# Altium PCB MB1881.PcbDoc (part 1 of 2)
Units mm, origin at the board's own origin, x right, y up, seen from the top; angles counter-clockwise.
Board outline 150 x 109 mm, 4 copper layers (Top Layer, Layer 1, Layer 2, Bottom Layer), stack 1.782 mm thick; 66 components, 175 nets, 880 pads, 302 vias.
Unrouted connection lines stored in the file: 35.
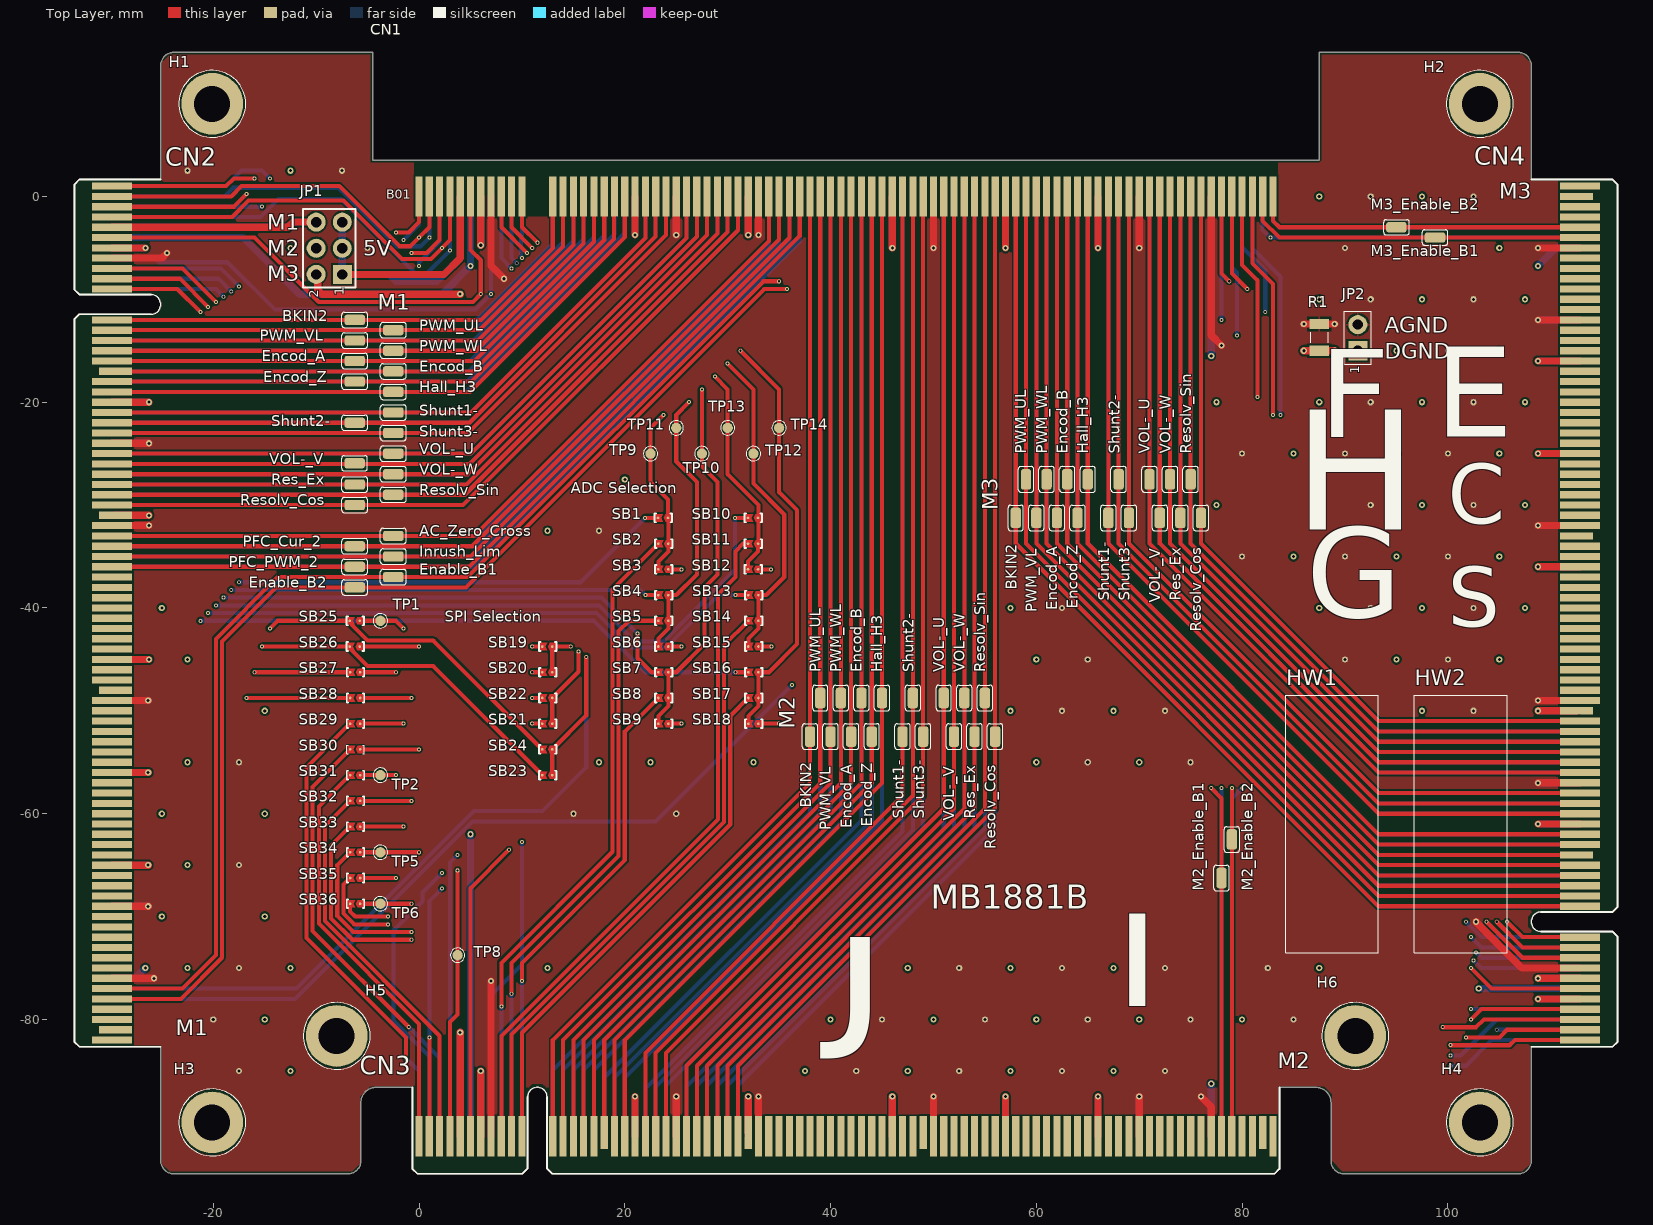
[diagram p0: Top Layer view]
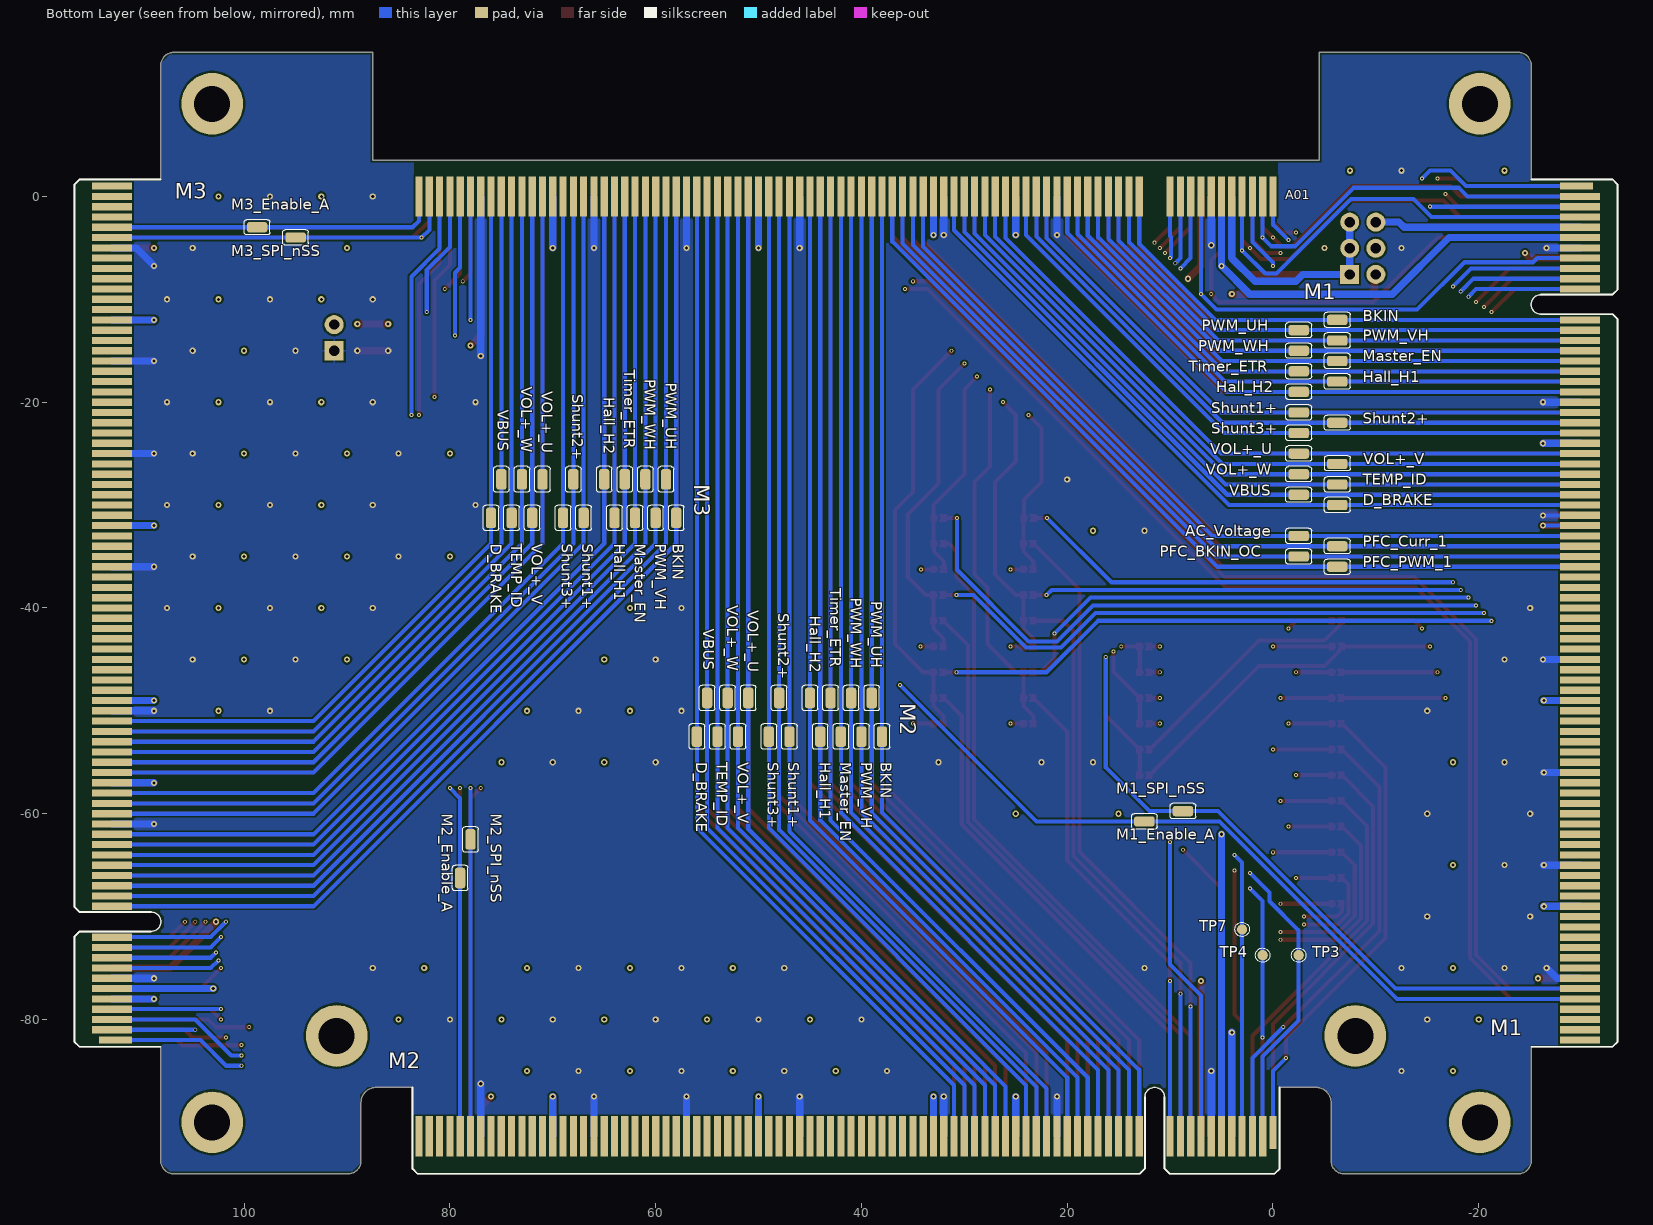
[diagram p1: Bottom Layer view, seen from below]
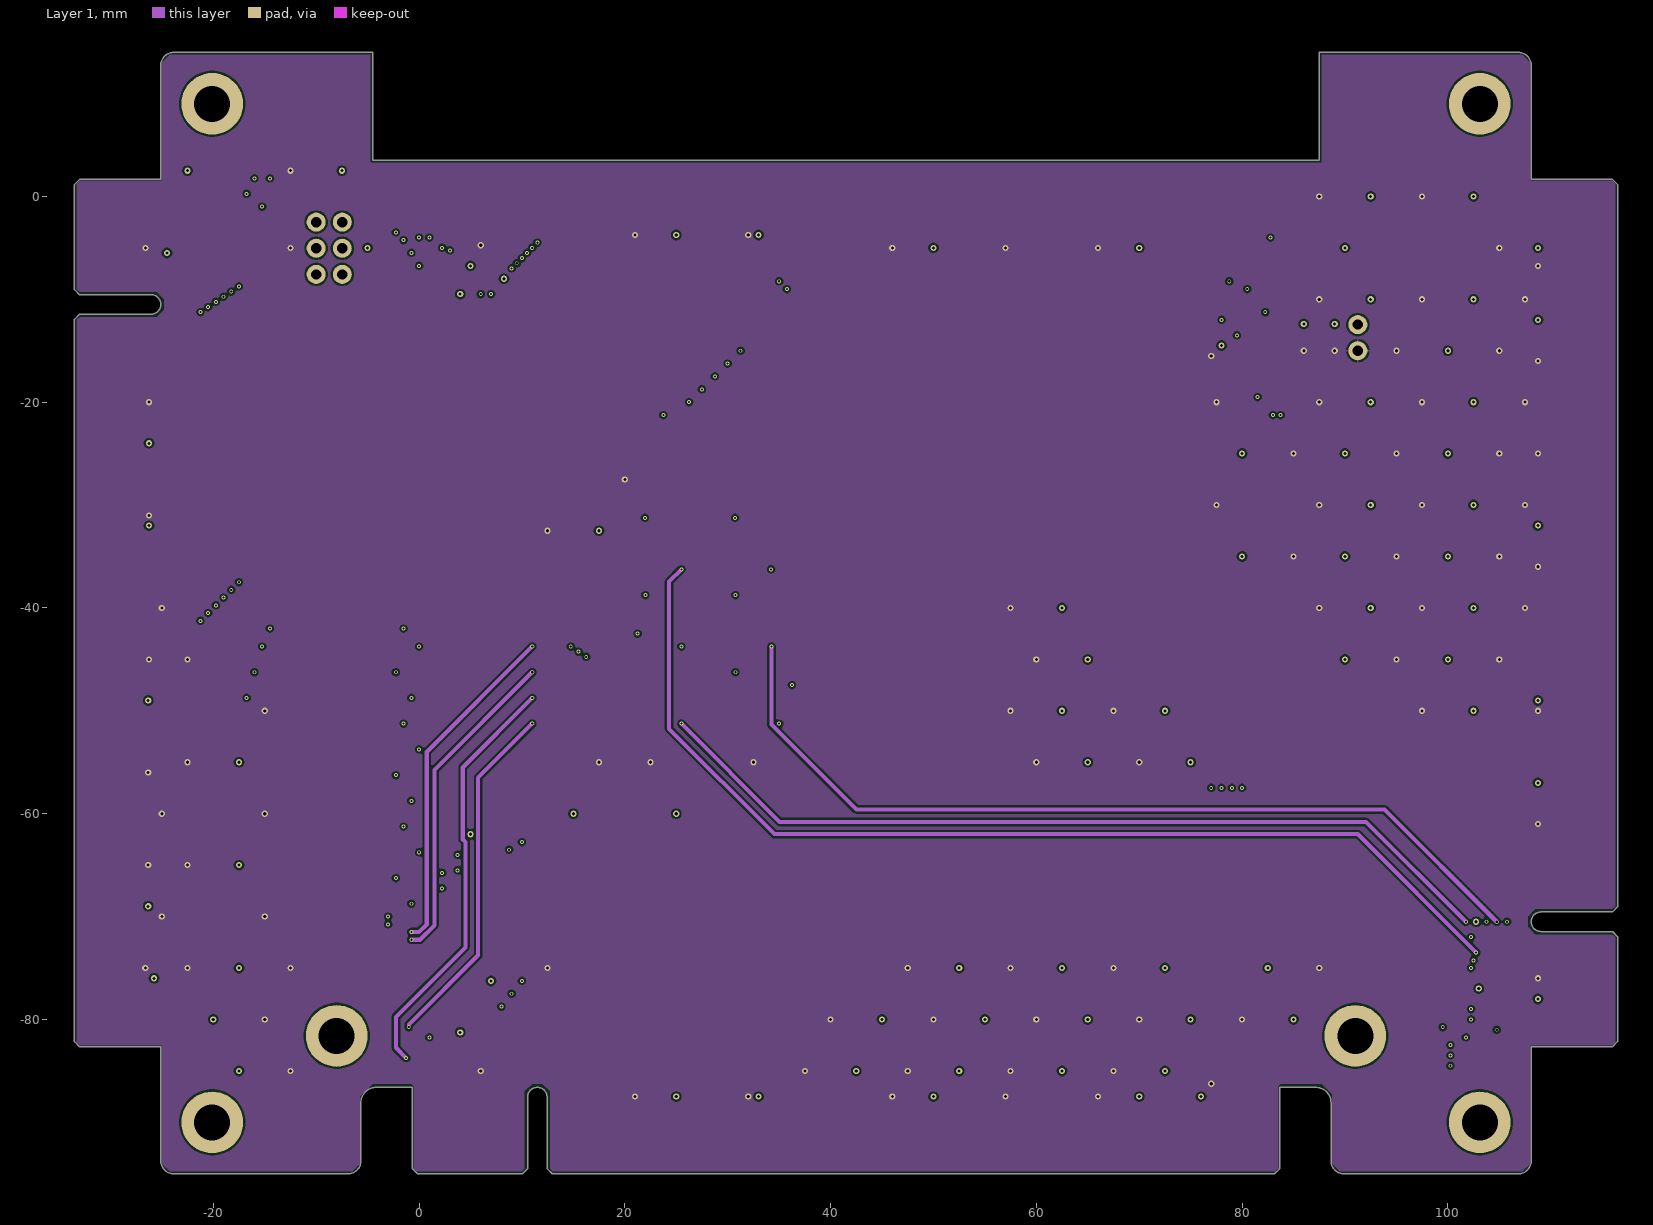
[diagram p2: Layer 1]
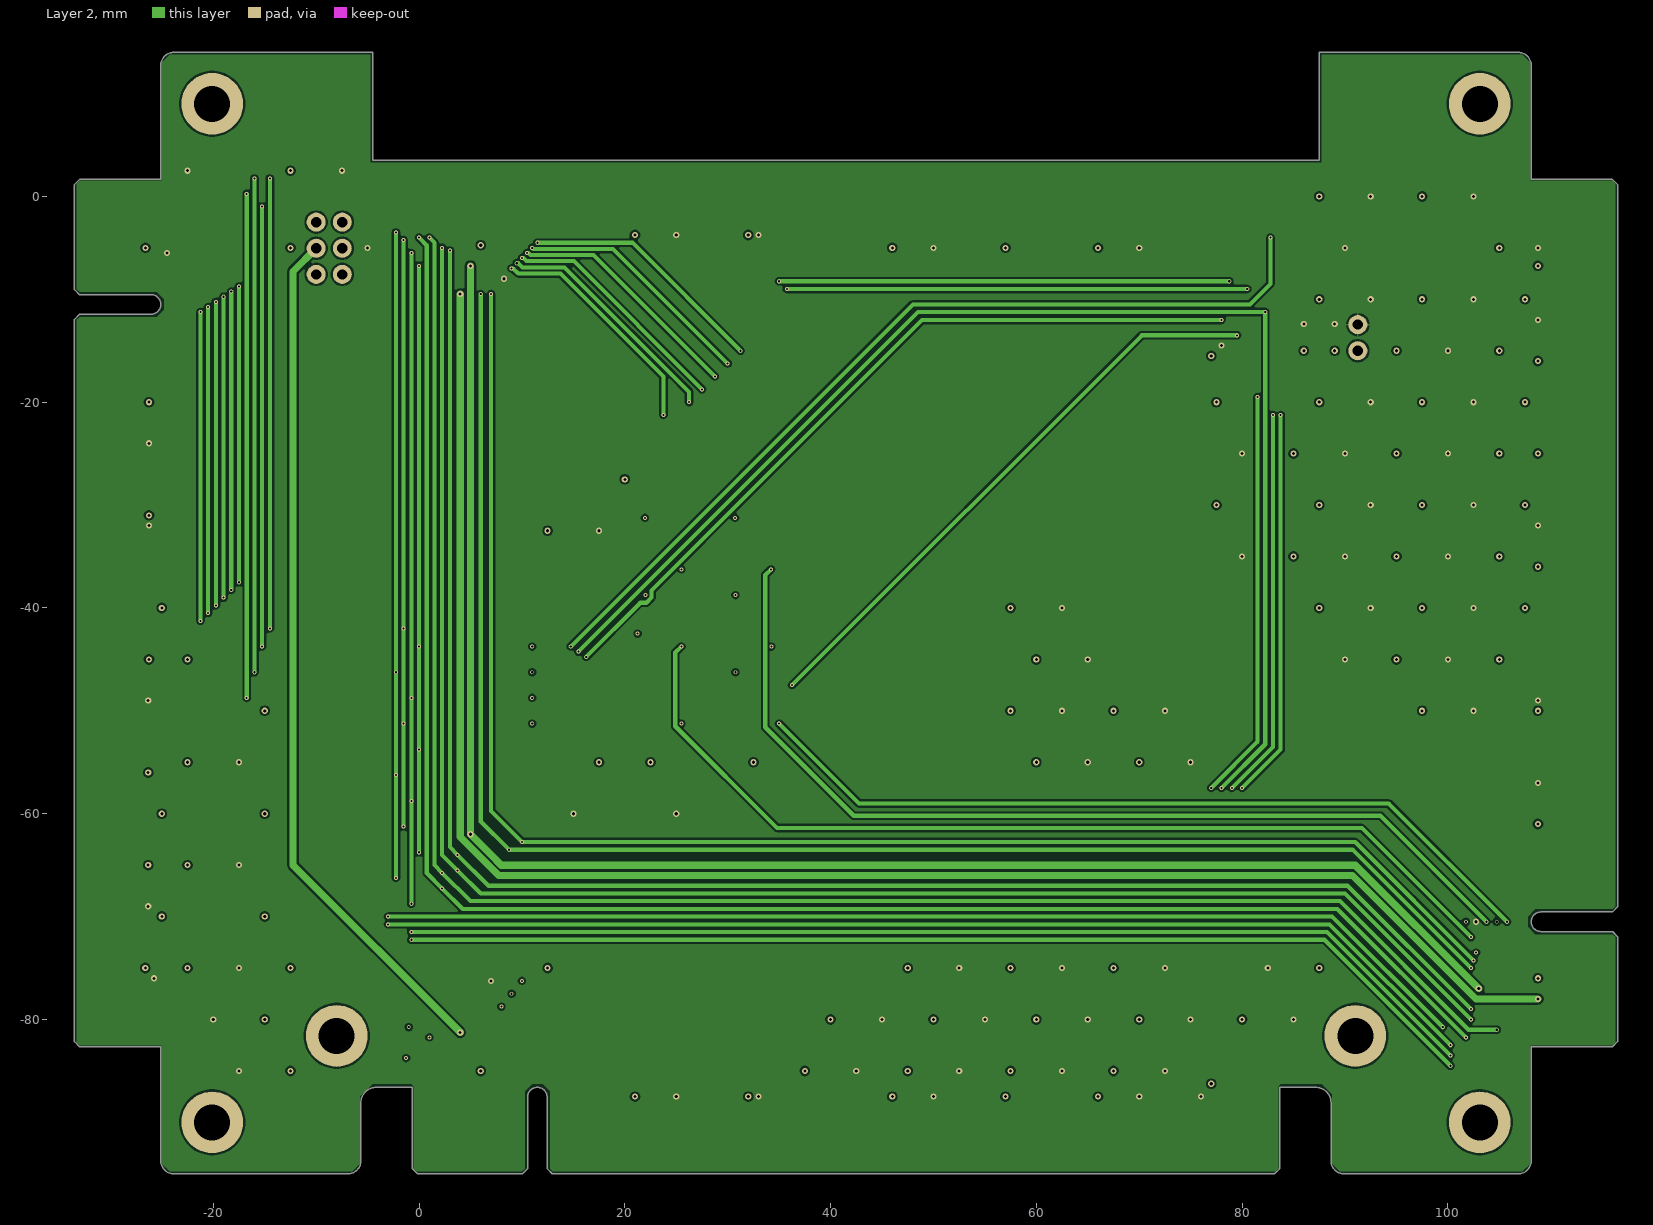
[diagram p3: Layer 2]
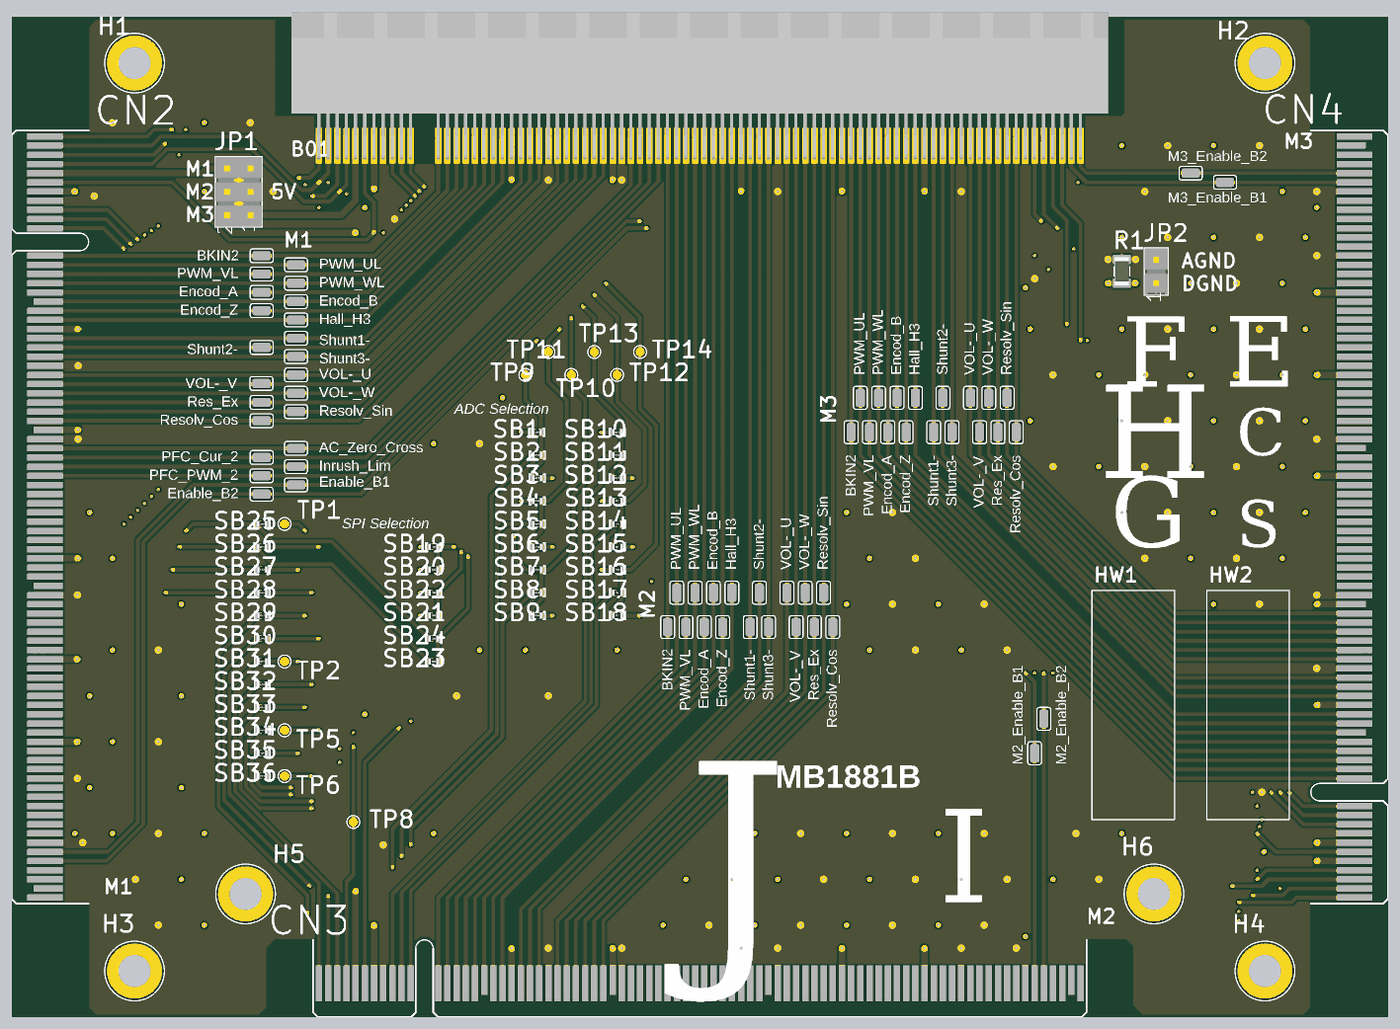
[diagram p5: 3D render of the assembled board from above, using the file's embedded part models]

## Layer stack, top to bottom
Top Solder: solder mask 0.015, Solder Resist, Dk 3.5
Top Layer: signal copper 0.035
Dielectric 2: prepreg 0.0711, PP-006, Dk 4.1
Layer 1: signal copper 0.035
Dielectric 1: dielectric 1.5, FR-4, Dk 4.8
Layer 2: signal copper 0.035
Dielectric 3: prepreg 0.0711, PP-006, Dk 4.1
Bottom Layer: signal copper 0.035
Bottom Solder: solder mask 0.015, Solder Resist, Dk 3.5

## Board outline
-25.1,-93.745 ccw(c-23.85,-93.745) -23.85,-94.995 -6.9,-94.995 ccw(c-6.9,-93.745) -5.65,-93.745 -5.65,-88.095 cw(c-4.15,-88.095) -4.15,-86.595 -0.65,-86.595 -0.65,-94.495 -0.15,-94.995 10.05,-94.995 10.525,-94.52 10.55,-94.495 10.55,-87.545 cw(c11.5,-87.545) 12.45,-87.545 12.45,-94.495 12.475,-94.52 12.95,-94.995 83.15,-94.995 83.625,-94.52 83.65,-94.495 83.65,-86.595 87.145,-86.595 cw(c87.145,-88.095) 88.645,-88.095 88.645,-93.745 ccw(c89.895,-93.745) 89.895,-94.995 106.85,-94.995 ccw(c106.85,-93.745) 108.1,-93.745 108.1,-82.65 116,-82.65 116.5,-82.15 116.5,-71.95 116.025,-71.475 116,-71.45 109.05,-71.45 cw(c109.05,-70.5) 109.05,-69.55 116,-69.55 116.5,-69.05 116.5,1.15 116,1.65 108.1,1.65 108.1,12.75 ccw(c106.85,12.75) 106.85,14 87.5,14 87.5,3.5 -4.5,3.5 -4.5,14 -23.85,14 ccw(c-23.85,12.75) -25.1,12.75 -25.1,1.65 -33,1.65 -33.5,1.15 -33.5,-9.05 -33.025,-9.525 -33,-9.55 -26.05,-9.55 cw(c-26.05,-10.5) -26.05,-11.45 -33,-11.45 -33.025,-11.475 -33.5,-11.95 -33.5,-82.15 -33,-82.65 -25.1,-82.65

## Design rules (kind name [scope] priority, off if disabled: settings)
Clearance Clearance_connector [WithinRoom('Connector')] p1: gap=0.1 ignorepadtopadclearanceinfootprint=FALSE
Clearance [All] p2: gap=0.198 ignorepadtopadclearanceinfootprint=FALSE
ComponentClearance [All] p1: gap=0.2 collisioncheckmode=3 verticalgap=0.2 showdistances=FALSE
HoleSize [All] p1: absolutevalues=TRUE maxlimit=10 minlimit=0.025 maxpercent=80.000 minpercent=20.000
MinimumSolderMaskSliver [All] p1: minsoldermaskwidth=0.076
PlaneConnect [All] p1: planeconnectstyle=Relief reliefexpansion=0.508 reliefentries=4 reliefconductorwidth=0.21 reliefairgap=0.21
PolygonConnect PolygonConnect_via [IsVia] p1: connectstyle=Direct reliefconductorwidth=0.254 reliefentries=4 polygonreliefangle="90 Angle" airgapwidth=0.254
PolygonConnect [All] p2: connectstyle=Relief reliefconductorwidth=0.2 reliefentries=4 polygonreliefangle="90 Angle" airgapwidth=0.2
RoomDefinition U_Mechanical [InComponentClass('U_Mechanical')] p1 off: confinementstyle=ConfineIn formatcopy=TRUE lockcomponents=FALSE outline 1.375,1.24 88.375,1.24 88.375,10.74 1.375,10.74
RoutingVias [All] p1: holewidth=0.203 width=0.381 viastyle="Through Hole" minholewidth=0.152 minwidth=0.305 maxholewidth=0.305 maxwidth=0.6
SilkToSilkClearance [All] p1: silktosilkclearance=0.102
SilkToSolderMaskClearance [IsPad] p1: minsilkscreentomaskgap=0.102 clearancetoexposedcopper=TRUE
SolderMaskExpansion [All] p1: expansion=0.102
Width Width_PWR [InNetClass('PWR')] p1: maxlimit=1.27 minlimit=0.254 preferedwidth=0.7 minimp=50.000000 maximp=50.000000 favimp=50.000000
Width [All] p2: maxlimit=1 minlimit=0.18 preferedwidth=0.4
24 further rules are at their usual default settings.

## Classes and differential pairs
component class U_Mechanical: H1 H2 H3 H4 H5 H6 HW1 HW2
component class U_Connectors: CN2 CN3 CN4
component class U_Configuration: JP1 JP2 R1 SB1 SB2 SB3 SB4 SB5 SB6 SB7 SB8 SB9 SB10 SB11 SB12 SB13 SB14 SB15 SB16 SB17 SB18 SB19 SB20 SB21 SB22 SB23 SB24 SB25 SB26 SB27 SB28 SB29 SB30 SB31 SB32 SB33 SB34 SB35 SB36

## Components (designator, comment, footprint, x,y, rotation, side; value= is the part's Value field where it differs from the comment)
CN1 "PCIE-164-02-X-D-EMS2" CON_SAMTEC_PCIE-164-02-X-D-EMS2 11.5,-1.225 r0 top locked value=Socket_PCIE-164-02-X-D-EMS2
CN2 "PCIE-Gold Finger-X16" CON_BOARD_GOLDFINGER_PCI_EXPRESS_X16 -29.855,-10.5 r270 top locked
CN3 "PCIE-Gold Finger-X16" CON_BOARD_GOLDFINGER_PCI_EXPRESS_X16 11.5,-91.35 r0 top locked value=N/A
CN4 "PCIE-Gold Finger-X16" CON_BOARD_GOLDFINGER_PCI_EXPRESS_X16 112.855,-70.5 r90 top locked
H1 "POSITION HOLE" PTH_M1261-3005-N_3P5X6_M3_H14 -20.1,9 r0 top locked
H2 "POSITION HOLE" PTH_M1261-3005-N_3P5X6_M3_H14 103.1,9 r0 top locked
H3 "POSITION HOLE" PTH_M1261-3005-N_3P5X6_M3_H14 -20.1,-90 r0 top locked
H4 "POSITION HOLE" PTH_M1261-3005-N_3P5X6_M3_H14 103.1,-90 r0 top locked
H5 "POSITION HOLE" PTH_M1261-3005-N_3P5X6_M3_H14 -8,-81.595 r0 top locked
H6 "POSITION HOLE" PTH_M1261-3005-N_3P5X6_M3_H14 91,-81.595 r0 top locked
HW1 "STICKER_PRODUCT" STICKER_PRODUCT_25X9 88.75,-61 r90 top value="Sticker product"
HW2 "MB1181" STICKER_BOARD_25X9 101.25,-61 r90 top value="Sticker board"
JP1 "Header 3x2" CON_SAMTEC_TSW-103-07-X-D -8.73,-5.04 r90 top value="Jumper_Header 3x2"
JP2 "Jumper_Header 2x1" CON_SAMTEC_TSW-102-07-G-S 91.25,-13.73 r90 top value="GND connect"
R1 "Resistor" R1206_H0P55 87.5,-13.7 r90 top value=0R
SB1 "SB_ON" SOLDER-BRIDGE_R0402-0R 23.75,-31.25 r180 top
SB2 "SB_OFF" SOLDER-BRIDGE_R0402-0R 23.788,-33.75 r180 top
SB3 "SB_OFF" SOLDER-BRIDGE_R0402-0R 23.788,-36.25 r180 top
SB4 "SB_ON" SOLDER-BRIDGE_R0402-0R 23.788,-38.75 r180 top
SB5 "SB_OFF" SOLDER-BRIDGE_R0402-0R 23.788,-41.25 r180 top
SB6 "SB_OFF" SOLDER-BRIDGE_R0402-0R 23.788,-43.75 r180 top
SB7 "SB_OFF" SOLDER-BRIDGE_R0402-0R 23.788,-46.25 r180 top
SB8 "SB_ON" SOLDER-BRIDGE_R0402-0R 23.788,-48.75 r180 top
SB9 "SB_OFF" SOLDER-BRIDGE_R0402-0R 23.788,-51.25 r180 top
SB10 "SB_OFF" SOLDER-BRIDGE_R0402-0R 32.5,-31.25 r180 top
SB11 "SB_ON" SOLDER-BRIDGE_R0402-0R 32.5,-33.75 r180 top
SB12 "SB_OFF" SOLDER-BRIDGE_R0402-0R 32.5,-36.25 r180 top
SB13 "SB_OFF" SOLDER-BRIDGE_R0402-0R 32.538,-38.75 r180 top
SB14 "SB_OFF" SOLDER-BRIDGE_R0402-0R 32.538,-41.25 r180 top
SB15 "SB_ON" SOLDER-BRIDGE_R0402-0R 32.538,-43.75 r180 top
SB16 "SB_OFF" SOLDER-BRIDGE_R0402-0R 32.538,-46.25 r180 top
SB17 "SB_OFF" SOLDER-BRIDGE_R0402-0R 32.538,-48.75 r180 top
SB18 "SB_ON" SOLDER-BRIDGE_R0402-0R 32.538,-51.25 r180 top
SB19 "SB_OFF" SOLDER-BRIDGE_R0402-0R 12.5,-43.75 r180 top
SB20 "SB_OFF" SOLDER-BRIDGE_R0402-0R 12.5,-46.25 r180 top
SB21 "SB_OFF" SOLDER-BRIDGE_R0402-0R 12.5,-51.25 r180 top
SB22 "SB_OFF" SOLDER-BRIDGE_R0402-0R 12.5,-48.75 r180 top
SB23 "SB_OFF" SOLDER-BRIDGE_R0402-0R 12.5,-56.25 r180 top
SB24 "SB_OFF" SOLDER-BRIDGE_R0402-0R 12.5,-53.75 r180 top
SB25 "SB_ON" SOLDER-BRIDGE_R0402-0R -6.212,-41.25 r180 top
SB26 "SB_ON" SOLDER-BRIDGE_R0402-0R -6.212,-43.75 r180 top
SB27 "SB_ON" SOLDER-BRIDGE_R0402-0R -6.175,-46.25 r180 top
SB28 "SB_ON" SOLDER-BRIDGE_R0402-0R -6.175,-48.75 r180 top
SB29 "SB_OFF" SOLDER-BRIDGE_R0402-0R -6.175,-51.25 r180 top
SB30 "SB_OFF" SOLDER-BRIDGE_R0402-0R -6.175,-53.75 r180 top
SB31 "SB_OFF" SOLDER-BRIDGE_R0402-0R -6.175,-56.25 r180 top
SB32 "SB_OFF" SOLDER-BRIDGE_R0402-0R -6.175,-58.75 r180 top
SB33 "SB_OFF" SOLDER-BRIDGE_R0402-0R -6.175,-61.25 r180 top
SB34 "SB_OFF" SOLDER-BRIDGE_R0402-0R -6.175,-63.75 r180 top
SB35 "SB_OFF" SOLDER-BRIDGE_R0402-0R -6.175,-66.25 r180 top
SB36 "SB_OFF" SOLDER-BRIDGE_R0402-0R -6.175,-68.75 r180 top
TP1 "Test Point" TP_SMD_1MM -3.75,-41.25 r90 top
TP2 "Test Point" TP_SMD_1MM -3.75,-56.25 r90 top
TP3 "Test Point" TP_SMD_1MM -2.5,-73.75 r90 bottom
TP4 "Test Point" TP_SMD_1MM 1,-73.75 r90 bottom
TP5 "Test Point" TP_SMD_1MM -3.75,-63.75 r90 top
TP6 "Test Point" TP_SMD_1MM -3.75,-68.75 r90 top
TP7 "Test Point" TP_SMD_1MM 3,-71.25 r90 bottom
TP8 "Test Point" TP_SMD_1MM 3.75,-73.75 r90 top
TP9 "Test Point" TP_SMD_1MM 22.5,-25 r90 top
TP10 "Test Point" TP_SMD_1MM 30,-22.5 r90 top
TP11 "Test Point" TP_SMD_1MM 25,-22.5 r90 top
TP12 "Test Point" TP_SMD_1MM 32.5,-25 r90 top
TP13 "Test Point" TP_SMD_1MM 27.5,-25 r90 top
TP14 "Test Point" TP_SMD_1MM 35,-22.5 r90 top
? "Comment" PCB_SPECIFICATIONS -44.25,117 r0 top

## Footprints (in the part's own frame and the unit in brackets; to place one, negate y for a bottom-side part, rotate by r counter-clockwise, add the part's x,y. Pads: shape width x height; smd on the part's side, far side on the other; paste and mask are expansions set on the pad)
CON_BOARD_GOLDFINGER_PCI_EXPRESS_X16 [mm] "MCD-02436"
  rect 0.7x3.2 smd far side mask+0.05: A01(-11.5,0.355)
  rect 0.7x3.91 smd far side mask+0.05: A02(-10.5,0) A03(-9.5,0) A04(-8.5,0) A05(-7.5,0) A06(-6.5,0) A07(-5.5,0) A08(-4.5,0) A09(-3.5,0) A10(-2.5,0) A11(-1.5,0) A12(1.5,0) A13(2.5,0) A14(3.5,0) A15(4.5,0) A16(5.5,0) A17(6.5,0) A18(7.5,0) A19(8.5,0) A20(9.5,0) A21(10.5,0) A22(11.5,0) A23(12.5,0) A24(13.5,0) A25(14.5,0) A26(15.5,0) A27(16.5,0) A28(17.5,0) A29(18.5,0) A30(19.5,0) A31(20.5,0) A32(21.5,0) A33(22.5,0) A34(23.5,0) A35(24.5,0) A36(25.5,0) A37(26.5,0) A38(27.5,0) A39(28.5,0) A40(29.5,0) A41(30.5,0) A42(31.5,0) A43(32.5,0) A44(33.5,0) A45(34.5,0) A46(35.5,0) A47(36.5,0) A48(37.5,0) A49(38.5,0) A50(39.5,0) A51(40.5,0) A52(41.5,0) A53(42.5,0) A54(43.5,0) A55(44.5,0) A56(45.5,0) A57(46.5,0) A58(47.5,0) A59(48.5,0) A60(49.5,0) A61(50.5,0) A62(51.5,0) A63(52.5,0) A64(53.5,0) A65(54.5,0) A66(55.5,0) A67(56.5,0) A68(57.5,0) A69(58.5,0) A70(59.5,0) A71(60.5,0) A72(61.5,0) A73(62.5,0) A74(63.5,0) A75(64.5,0) A76(65.5,0) A77(66.5,0) A78(67.5,0) A79(68.5,0) A80(69.5,0) A81(70.5,0) A82(71.5,0)
  rect 0.7x3.91 smd mask+0.05: B01(-11.5,0) B02(-10.5,0) B03(-9.5,0) B04(-8.5,0) B05(-7.5,0) B06(-6.5,0) B07(-5.5,0) B08(-4.5,0) B09(-3.5,0) B10(-2.5,0) B11(-1.5,0) B12(1.5,0) B13(2.5,0) B14(3.5,0) B15(4.5,0) B16(5.5,0) B18(7.5,0) B19(8.5,0) B20(9.5,0) B21(10.5,0) B22(11.5,0) B23(12.5,0) B24(13.5,0) B25(14.5,0) B26(15.5,0) B27(16.5,0) B28(17.5,0) B29(18.5,0) B30(19.5,0) B32(21.5,0) B33(22.5,0) B34(23.5,0) B35(24.5,0) B36(25.5,0) B37(26.5,0) B38(27.5,0) B39(28.5,0) B40(29.5,0) B41(30.5,0) B42(31.5,0) B43(32.5,0) B44(33.5,0) B45(34.5,0) B46(35.5,0) B47(36.5,0) B49(38.5,0) B50(39.5,0) B51(40.5,0) B52(41.5,0) B53(42.5,0) B54(43.5,0) B55(44.5,0) B56(45.5,0) B57(46.5,0) B58(47.5,0) B59(48.5,0) B60(49.5,0) B61(50.5,0) B62(51.5,0) B63(52.5,0) B64(53.5,0) B65(54.5,0) B66(55.5,0) B67(56.5,0) B68(57.5,0) B69(58.5,0) B70(59.5,0) B71(60.5,0) B72(61.5,0) B73(62.5,0) B74(63.5,0) B75(64.5,0) B76(65.5,0) B77(66.5,0) B78(67.5,0) B79(68.5,0) B80(69.5,0) B82(71.5,0)
  rect 0.7x3.2 smd mask+0.05: B17(6.5,0.355) B31(20.5,0.355) B48(37.5,0.355) B81(70.5,0.355)
  silkscreen extent -12.15,-3.64 72.15,4.76
CON_SAMTEC_PCIE-164-02-X-D-EMS2 [mm] "MCD-02913"
  rect 0.7x3.91 smd far side paste-1 mask+0.05: A01(-11.5,1.225) A02(-10.5,1.225) A03(-9.5,1.225) A04(-8.5,1.225) A05(-7.5,1.225) A06(-6.5,1.225) A07(-5.5,1.225) A08(-4.5,1.225) A09(-3.5,1.225) A10(-2.5,1.225) A11(-1.5,1.225) A12(1.5,1.225) A13(2.5,1.225) A14(3.5,1.225) A15(4.5,1.225) A16(5.5,1.225) A17(6.5,1.225) A18(7.5,1.225) A19(8.5,1.225) A20(9.5,1.225) A21(10.5,1.225) A22(11.5,1.225) A23(12.5,1.225) A24(13.5,1.225) A25(14.5,1.225) A26(15.5,1.225) A27(16.5,1.225) A28(17.5,1.225) A29(18.5,1.225) A30(19.5,1.225) A31(20.5,1.225) A32(21.5,1.225) A33(22.5,1.225) A34(23.5,1.225) A35(24.5,1.225) A36(25.5,1.225) A37(26.5,1.225) A38(27.5,1.225) A39(28.5,1.225) A40(29.5,1.225) A41(30.5,1.225) A42(31.5,1.225) A43(32.5,1.225) A44(33.5,1.225) A45(34.5,1.225) A46(35.5,1.225) A47(36.5,1.225) A48(37.5,1.225) A49(38.5,1.225) A50(39.5,1.225) A51(40.5,1.225) A52(41.5,1.225) A53(42.5,1.225) A54(43.5,1.225) A55(44.5,1.225) A56(45.5,1.225) A57(46.5,1.225) A58(47.5,1.225) A59(48.5,1.225) A60(49.5,1.225) A61(50.5,1.225) A62(51.5,1.225) A63(52.5,1.225) A64(53.5,1.225) A65(54.5,1.225) A66(55.5,1.225) A67(56.5,1.225) A68(57.5,1.225) A69(58.5,1.225) A70(59.5,1.225) A71(60.5,1.225) A72(61.5,1.225) A73(62.5,1.225) A74(63.5,1.225) A75(64.5,1.225) A76(65.5,1.225) A77(66.5,1.225) A78(67.5,1.225) A79(68.5,1.225) A80(69.5,1.225) A81(70.5,1.225) A82(71.5,1.225)
  rect 0.7x3.91 smd paste-1 mask+0.05: B01(-11.5,1.225) B02(-10.5,1.225) B03(-9.5,1.225) B04(-8.5,1.225) B05(-7.5,1.225) B06(-6.5,1.225) B07(-5.5,1.225) B08(-4.5,1.225) B09(-3.5,1.225) B10(-2.5,1.225) B11(-1.5,1.225) B12(1.5,1.225) B13(2.5,1.225) B14(3.5,1.225) B15(4.5,1.225) B16(5.5,1.225) B17(6.5,1.225) B18(7.5,1.225) B19(8.5,1.225) B20(9.5,1.225) B21(10.5,1.225) B22(11.5,1.225) B23(12.5,1.225) B24(13.5,1.225) B25(14.5,1.225) B26(15.5,1.225) B27(16.5,1.225) B28(17.5,1.225) B29(18.5,1.225) B30(19.5,1.225) B31(20.5,1.225) B32(21.5,1.225) B33(22.5,1.225) B34(23.5,1.225) B35(24.5,1.225) B36(25.5,1.225) B37(26.5,1.225) B38(27.5,1.225) B39(28.5,1.225) B40(29.5,1.225) B41(30.5,1.225) B42(31.5,1.225) B43(32.5,1.225) B44(33.5,1.225) B45(34.5,1.225) B46(35.5,1.225) B47(36.5,1.225) B48(37.5,1.225) B49(38.5,1.225) B50(39.5,1.225) B51(40.5,1.225) B52(41.5,1.225) B53(42.5,1.225) B54(43.5,1.225) B55(44.5,1.225) B56(45.5,1.225) B57(46.5,1.225) B58(47.5,1.225) B59(48.5,1.225) B60(49.5,1.225) B61(50.5,1.225) B62(51.5,1.225) B63(52.5,1.225) B64(53.5,1.225) B65(54.5,1.225) B66(55.5,1.225) B67(56.5,1.225) B68(57.5,1.225) B69(58.5,1.225) B70(59.5,1.225) B71(60.5,1.225) B72(61.5,1.225) B73(62.5,1.225) B74(63.5,1.225) B75(64.5,1.225) B76(65.5,1.225) B77(66.5,1.225) B78(67.5,1.225) B79(68.5,1.225) B80(69.5,1.225) B81(70.5,1.225) B82(71.5,1.225)
  body extent -14.5,-0.26 74.5,15.8, height 4.22
CON_SAMTEC_TSW-102-07-G-S [mm]
  rect 1.85x1.85 / inner round 1.85 / far side rect 1.85x1.85 hole 1 mask+0.05: 1(-1.27,0)
  round 1.85 hole 1 mask+0.05: 2(1.27,0)
  silkscreen extent -2.58,-1.3 2.58,1.3, body extent -2.67,-1.3 2.58,1.3, height 8.38
CON_SAMTEC_TSW-103-07-X-D [mm]
  rect 1.85x1.85 / inner round 1.85 / far side rect 1.85x1.85 hole 1 mask+0.05: 1(-2.54,-1.27)
  round 1.85 hole 1 mask+0.05: 2(-2.54,1.27) 3(0,-1.27) 4(0,1.27) 5(2.54,-1.27) 6(2.54,1.27)
  silkscreen extent -3.81,-2.54 3.81,2.54, body extent -3.81,-2.54 3.81,2.54, height 8.38
PCB_SPECIFICATIONS [mm]
PTH_M1261-3005-N_3P5X6_M3_H14 [mm]
  round 6 hole 3.5 mask+0.05: 1(0,0)
  silkscreen extent -3.25,-3.25 3.25,3.25, body extent -2.5,-2.5 2.5,2.5, height 5
R1206_H0P55 [mm]
  rect 1x1.9 smd mask+0.05: 1(-1.3,0) 2(1.3,0)
  silkscreen extent -0.5,-0.85 0.5,0.85, body extent -1.6,-0.85 1.6,0.85, height 0.65
SOLDER-BRIDGE_R0402-0R [mil] "MCD-01619"
  round 10 smd paste-393.7: 1(-17.72,0) 2(20.67,0)
  Top Layer region: -30.51,-13.78 -30.51,13.78 -8.37,13.78 -1.48,0 -8.37,-13.78
  Top Layer region: 1.48,13.78 8.37,0 1.48,-13.78 30.51,-13.78 30.51,13.78
  silkscreen extent -33,-17 33,17, body extent -20,-12 20,12, height 14
STICKER_BOARD_25X9 [mm] "Sticker to mention board CPN code"
  silkscreen extent -12.5,-4.5 12.5,4.5
STICKER_PRODUCT_25X9 [mm] "Sticker to mention board CPN code"
  silkscreen extent -12.5,-4.5 12.5,4.5
TP_SMD_1MM [mm]
  round 1 smd paste-10 mask+0.05: 1(0,0)
  silkscreen extent -0.7,-0.7 0.7,0.7

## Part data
CN1: library part MCD-02913, "1.00 mm PCI Express Edge Card Connector", Manufacturer=SAMTEC
CN2 CN3 CN4: library part MCD-02436, "PCI EXPRESS x16 Add-in Card Edge-Finger", Manufacturer=N/A
H1 H2 H3 H4 H5 H6: library part MCD-00035, "POSITION HOLE C6D3R5", Manufacturer=N/A, Manufacturer_Part_Number=n/a
HW1: library part MCD-00547, "Sticker product 25x9 mm", Manufacturer=N/A
HW2: library part MCD-00235, "Sticker Board 25x9 mm", Manufacturer=N/A
JP1: library part MCD-00233, "Header, 3x2, 2.54mm, VR, TH, T=5.84mm/2.54mm", Manufacturer=SAMTEC, Manufacturer_Part_Number=TSW-103-07-G-D
JP2: library part MCD-02390, "Header, 2x1, 2,54mm, VR, TH, T=6mm/3mm", Manufacturer=MTCONN, Manufacturer_Part_Number=JT254-D180-102-001
R1: library part MCD-00180, "Resistor, 0R, 1206, +/-5%, 1/4W", Manufacturer=YAGEO, Manufacturer_Part_Number=RC1206JR-070RL, Package=1206
SB1 SB4 SB8 SB11 SB15 SB18 SB25 SB26 SB27 SB28: library part MCD-01618, "Solder Bridge 0402 ON", Manufacturer=YAGEO, Manufacturer_Part_Number=RC0402JR-070RL, Package=SB0402
SB2 SB3 SB5 SB6 SB7 SB9 SB10 SB12 SB13 SB14 SB16 SB17 SB19 SB20 SB21 SB22 SB23 SB24 SB29 SB30 SB31 SB32 SB33 SB34 SB35 SB36: library part MCD-02162, "Solder Bridge 0402 OFF", Manufacturer=YAGEO, Manufacturer_Part_Number=RC0402JR-070RL, Package=SB0402
TP1 TP2 TP3 TP4 TP5 TP6 TP7 TP8 TP9 TP10 TP11 TP12 TP13 TP14: library part MCD-00074, "Test Point 1mm", Manufacturer=N/A

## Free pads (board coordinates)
  rrect50% 2x1 smd: TP(-6.267,-25.933) TP(-6.25,-38) TP(-6.25,-36) TP(-6.25,-34) TP(-6.25,-30) TP(-6.25,-28) TP(-6.25,-22) TP(-6.25,-18) TP(-6.25,-16) TP(-6.25,-14) TP(-6.25,-12) TP(-2.5,-37) TP(-2.5,-35) TP(-2.5,-33) TP(-2.5,-29) TP(-2.5,-27) TP(-2.5,-25) TP(-2.5,-23) TP(-2.5,-21) TP(-2.5,-19) TP(-2.5,-17) TP(-2.5,-15) TP(-2.5,-13) TP(95,-3) TP(98.75,-4)
  rrect50% 2x1 smd far side: TP(-6.25,-36) TP(-6.25,-34) TP(-6.25,-30) TP(-6.25,-28) TP(-6.25,-26) TP(-6.25,-22) TP(-6.25,-18) TP(-6.25,-16) TP(-6.25,-14) TP(-6.25,-12) TP(-2.5,-35) TP(-2.5,-33) TP(-2.5,-29) TP(-2.5,-27) TP(-2.5,-25) TP(-2.5,-23) TP(-2.5,-21) TP(-2.5,-19) TP(-2.5,-17) TP(-2.5,-15) TP(-2.5,-13) TP(8.75,-59.75) TP(12.5,-60.75) TP(95,-4) TP(98.74,-3)
  rrect50% 1x2 smd: TP(38,-52.5) TP(39,-48.75) TP(40,-52.5) TP(41,-48.75) TP(42,-52.5) TP(43,-48.75) TP(44,-52.5) TP(45,-48.75) TP(47,-52.5) TP(48,-48.75) TP(49,-52.5) TP(51,-48.75) TP(52,-52.5) TP(53,-48.75) TP(54,-52.5) TP(55,-48.75) TP(56,-52.5) TP(58,-31.25) TP(59,-27.5) TP(60,-31.25) TP(61,-27.5) TP(62,-31.25) TP(63,-27.5) TP(64,-31.25) TP(65,-27.5) TP(67,-31.25) TP(68,-27.5) TP(69,-31.25) TP(71,-27.5) TP(72,-31.25) TP(73,-27.5) TP(74,-31.25) TP(75,-27.5) TP(76,-31.25) TP(78,-66.25) TP(79,-62.5)
  rrect50% 1x2 smd far side: TP(38,-52.5) TP(39,-48.75) TP(40,-52.5) TP(41,-48.75) TP(42,-52.5) TP(43,-48.75) TP(44,-52.5) TP(45,-48.75) TP(47,-52.5) TP(48,-48.75) TP(49,-52.5) TP(51,-48.75) TP(52,-52.5) TP(53,-48.75) TP(54,-52.5) TP(55,-48.75) TP(56,-52.5) TP(58,-31.25) TP(59,-27.5) TP(60,-31.25) TP(61,-27.5) TP(62,-31.25) TP(63,-27.5) TP(64,-31.25) TP(65,-27.5) TP(67,-31.25) TP(68,-27.5) TP(69,-31.25) TP(71,-27.5) TP(72,-31.25) TP(73,-27.5) TP(74,-31.25) TP(75,-27.5) TP(76,-31.25) TP(78,-62.5) TP(79,-66.25)

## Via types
v1: diameter 0.6, hole 0.3, Top Layer to Bottom Layer, 181 vias
v2: diameter 0.381, hole 0.203, Top Layer to Bottom Layer, 121 vias

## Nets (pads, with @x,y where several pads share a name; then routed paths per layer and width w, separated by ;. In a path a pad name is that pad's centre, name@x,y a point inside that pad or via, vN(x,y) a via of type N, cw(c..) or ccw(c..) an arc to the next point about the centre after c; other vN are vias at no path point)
3.3V_to_PWRB: CN1.A06 CN2.A06 CN3.A06 CN4.A06 | length 243.7
  Layer 2 w0.7: v1(5,-6.75) v1(5,-62) 7,-64 8,-65 91,-65 v1(103,-77)
  Bottom Layer w0.7: CN2.A06@-29.855,-4 -17.1,-4 -11.6,-9.5 2.25,-9.5 v1(5,-6.75) CN1.A06@5,0 ; CN3.A06@5,-91.35 v1(5,-62) ; v1(103,-77) CN4.A06@112.855,-77
5V_to_CTRLB: CN1.A05 CN1.B05 JP1.1 JP1.3 JP1.5 | length 41.9
  Top Layer w0.7: JP1.1@-7.46,-7.58 2.42,-7.58 4,-6 CN1.B05@4,0
  Bottom Layer w0.7: JP1.5@-7.46,-2.5 JP1.3@-7.46,-5.04 JP1.1@-7.46,-7.58 -2.901,-7.58 -2.232,-8.248 1.752,-8.248 4,-6 CN1.A05@4,0
AC_Voltage: CN1.A33 CN2.A33 pad.TP@-2.5,-33 | length 80.4
  Bottom Layer w0.4: CN2.A33@-29.855,-33 5.865,-33 34,-4.866 CN1.A33@34,0
AC_Zero_Crossing: CN1.B33 CN2.B33 pad.TP@-2.5,-33 | length 80.1
  Top Layer w0.4: CN2.B33@-29.855,-33 5.328,-33 34,-4.328 CN1.B33@34,0
ADC_1: CN1.A09 SB1.1 SB2.1 SB3.2 TP9.1 | length 46.9
  Top Layer w0.4: SB3.2@23.263,-36.25 23.263,-35.488 24.238,-34.513 SB2.1@24.238,-33.75 SB1.1@24.238,-31.25 ; v2(23.75,-21.25) 22.5,-22.5 TP9.1@22.5,-25 22.5,-27.75 24.2,-29.45 SB1.1@24.2,-31.25
  Layer 2 w0.4: v2(9,-7) 9.154,-7 9.645,-7.491 13.741,-7.491 23.75,-17.5 v2(23.75,-21.25)
  Bottom Layer w0.4: CN1.A09@8,0 8,-6 v2(9,-7)
ADC_2: CN1.A10 SB4.1 SB5.1 SB6.2 TP11.1 | length 56.7
  Top Layer w0.4: SB6.2@23.263,-43.75 23.263,-42.988 24.238,-42.013 SB5.1@24.238,-41.25 SB4.1@24.238,-38.75 25,-38.75 27,-36.75 27,-27.75 25,-25.75 TP11.1@25,-22.5 25,-21.25 v2(26.25,-20)
  Layer 2 w0.4: v2(9.5,-6.5) 9.654,-6.5 10.047,-6.892 14.142,-6.892 26.25,-19 v2(26.25,-20)
  Bottom Layer w0.4: CN1.A10@9,0 9,-6 v2(9.5,-6.5)
ADC_3: CN1.A11 SB7.1 SB8.1 SB9.2 TP13.1 | length 64.8
  Top Layer w0.4: SB9.2@23.263,-51.25 23.263,-50.488 24.238,-49.513 SB8.1@24.238,-48.75 SB7.1@24.238,-46.25 25,-46.25 27.75,-43.5 27.75,-38 29,-36.75 29,-27.75 27.5,-26.25 TP13.1@27.5,-25 v2(27.5,-18.75)
  Layer 2 w0.4: v2(10,-6) 10.154,-6 10.448,-6.294 15.044,-6.294 v2(27.5,-18.75)
  Bottom Layer w0.4: v2(10,-6) 9.911,-5.911 9.911,-3.95 10,-3.861 CN1.A11@10,0
ADC_4: CN1.B09 SB10.1 SB11.1 SB12.2 TP10.1 | length 50.7
  Top Layer w0.4: CN1.B09@8,0 8,-3 v2(10.5,-5.5) ; v2(28.75,-17.5) 30,-18.75 30,-27 32.988,-29.988 32.988,-31.25 32.988,-33.713 SB11.1@32.95,-33.75 32.95,-34.513 31.975,-35.488 SB12.2@31.975,-36.25
  Layer 2 w0.4: v2(10.5,-5.5) 10.654,-5.5 10.85,-5.696 16.946,-5.696 v2(28.75,-17.5)
ADC_5: CN1.B10 SB13.1 SB14.1 SB15.2 TP12.1 | length 61.2
  Top Layer w0.4: CN1.B10@9,0 9,-3 v2(11,-5) ; v2(30,-16.25) 32.5,-18.75 32.5,-27.904 35.5,-30.904 35.5,-37 33.75,-38.75 SB13.1@32.988,-38.75 SB14.1@32.988,-41.25 32.988,-42.013 32.013,-42.988 SB15.2@32.013,-43.75
  Layer 2 w0.4: v2(11,-5) 11.098,-5.098 18.848,-5.098 v2(30,-16.25)
ADC_6: CN1.B11 SB16.1 SB17.1 SB18.2 TP14.1 | length 70.3
  Top Layer w0.4: CN1.B11@10,0 10,-3 v2(11.5,-4.5) ; v2(31.25,-15) 35,-18.75 35,-25 35,-28.75 36.75,-30.5 36.75,-43.5 34,-46.25 SB16.1@32.988,-46.25 SB17.1@32.988,-48.75 32.988,-49.513 32.013,-50.488 SB18.2@32.013,-51.25
  Layer 2 w0.4: v2(11.5,-4.5) 20.75,-4.5 v2(31.25,-15)
AGND: CN1.A24 CN1.A32 CN1.A49 CN1.A69 CN1.B08 CN1.B24 CN1.B32 CN1.B49 CN1.B69 CN1.B76 CN2.A24 CN2.A32 CN2.A49 CN2.A69 CN2.B08 CN2.B24 CN2.B32 CN2.B49 CN2.B69 CN2.B76 CN3.A24 CN3.A32 CN3.A49 CN3.A69 CN3.B08 CN3.B24 CN3.B32 CN3.B49 CN3.B69 CN3.B76 CN4.A24 CN4.A32 CN4.A49 CN4.A69 CN4.B08 CN4.B24 CN4.B32 CN4.B49 CN4.B69 CN4.B76 JP2.2 R1.2 | length 198.8
  Top Layer w0.7: CN2.B76@-29.855,-76 v1(-25.75,-76) ; CN2.B69@-29.855,-69 v1(-26.325,-69) ; CN2.B49@-29.855,-49 v1(-26.325,-49) ; CN2.B32@-29.855,-32 v1(-26.25,-32) ; CN2.B24@-29.855,-24 v1(-26.25,-24) ; CN2.B08@-29.855,-6 -25,-6 v1(-24.5,-5.5) ; CN3.B08@7,-91.35 v1(7,-76.25) ; CN1.B08@7,0 7,-6.75 v1(8.25,-8) ; CN3.B24@25,-91.35 v1(25,-87.5) ; v1(25,-3.75) CN1.B24@25,0 ; CN3.B32@33,-91.35 33,-89.54 v1(33,-87.5) ; v1(33,-3.75) CN1.B32@33,0 ; CN3.B49@50,-91.35 v1(50,-87.5) ; v1(50,-5) CN1.B49@50,0 ; CN3.B69@70,-91.35 v1(70,-87.5) ; v1(70,-5) CN1.B69@70,0 ; v1(76,-87.5) 77,-88.5 CN3.B76@77,-91.35 ; CN1.B76@77,0 77,-13.5 v1(78,-14.5) ; v1(86,-12.4) R1.2@87.5,-12.4 v1(89,-12.4) ; v1(102.75,-70.5) 102.75,-70.558 107.192,-75 CN4.B08@112.855,-75 ; v1(108.75,-32) CN4.B49@112.855,-32 ; v1@108.75,-12 CN4.B69@112.855,-12 ; v1(108.75,-57) CN4.B24@112.855,-57 ; v1(108.75,-49) CN4.B32@112.855,-49 ; v1(108.75,-5) CN4.B76@112.855,-5
  Bottom Layer w0.4: CN2.A32@-29.855,-32 v1(-26.25,-32)
  Bottom Layer w0.7: CN2.A69@-29.855,-69 v1(-26.325,-69) ; CN2.A49@-29.855,-49 v1(-26.325,-49) ; CN2.A24@-29.855,-24 v1(-26.25,-24) ; CN3.A24@25,-91.35 v1(25,-87.5) ; v1(25,-3.75) CN1.A24@25,0 ; CN3.A32@33,-91.35 33,-89.54 v1(33,-87.5) ; v1(33,-3.75) CN1.A32@33,0 ; CN3.A49@50,-91.35 v1(50,-87.5) ; v1(50,-5) CN1.A49@50,0 ; CN3.A69@70,-91.35 v1(70,-87.5) ; v1(70,-5) CN1.A69@70,0 ; v1(108.75,-32) CN4.A49@112.855,-32 ; v1@108.75,-12 CN4.A69@112.855,-12 ; v1(108.75,-57) CN4.A24@112.855,-57 ; v1(108.75,-49) CN4.A32@112.855,-49
  other v1: -17.5,-85 42.5,-85 52.5,-85 62.5,-85 72.5,-85 -20,-80 45,-80 55,-80 65,-80 75,-80 85,-80 -17.5,-75 52.5,-75 62.5,-75 72.5,-75 82.5,-75 -17.5,-65 15,-60 25,-60 -17.5,-55 65,-55 75,-55 62.5,-50 72.5,-50 102.5,-50 65,-45 90,-45 100,-45 62.5,-40 92.5,-40 102.5,-40 80,-35 90,-35 100,-35 17.5,-32.5 92.5,-30 102.5,-30 80,-25 90,-25 100,-25 92.5,-20 102.5,-20 100,-15 108.75,-12 92.5,-10 102.5,-10 -5,-5 90,-5 92.5,0 102.5,0 -22.5,2.5 -7.5,2.5
DGND: CN1.A07 CN1.A20 CN1.A31 CN1.A45 CN1.A56 CN1.A65 CN1.A76 CN1.B07 CN1.B20 CN1.B31 CN1.B45 CN1.B56 CN1.B65 CN2.A07 CN2.A20 CN2.A31 CN2.A45 CN2.A56 CN2.A65 CN2.A76 CN2.B07 CN2.B20 CN2.B31 CN2.B45 CN2.B56 CN2.B65 CN3.A07 CN3.A20 CN3.A31 CN3.A45 CN3.A56 CN3.A65 CN3.A76 CN3.B07 CN3.B20 CN3.B31 CN3.B45 CN3.B56 CN3.B65 CN4.A07 CN4.A20 CN4.A31 CN4.A45 CN4.A56 CN4.A65 CN4.A76 CN4.B07 CN4.B20 CN4.B31 CN4.B45 CN4.B56 CN4.B65 JP2.1 R1.1 | length 228.4
  Top Layer w0.7: CN2.B65@-29.855,-65 v1(-26.325,-65) ; CN2.B56@-29.855,-56 v1(-26.325,-56) ; CN2.B45@-29.855,-45 v1(-26.25,-45) ; CN2.B20@-29.855,-20 v1(-26.25,-20) ; CN2.B07@-29.855,-5 v1(-26.59,-5) ; CN2.B31@-29.5,-31 v1(-26.25,-31) ; CN3.B07@6,-91.35 v1(6,-85) ; v1(6,-4.75) CN1.B07@6,0 ; CN3.B20@21,-91.35 v1(21,-87.5) ; v1(21,-3.75) CN1.B20@21,0 ; CN3.B31@32,-90.995 v1(32,-87.5) ; v1(32,-3.75) CN1.B31@32,0 ; CN3.B45@46,-91.35 v1(46,-87.5) ; v1(46,-5) CN1.B45@46,0 ; CN3.B56@57,-91.35 v1(57,-87.5) ; v1(57,-5) CN1.B56@57,0 ; CN3.B65@66,-91.35 v1(66,-87.5) ; v1(66,-5) CN1.B65@66,0 ; v1(86,-15) R1.1@87.5,-15 v1(89,-15) ; v1(108.75,-36) CN4.B45@112.855,-36 ; v1(108.75,-25) CN4.B56@112.855,-25 ; v1(108.75,-16) CN4.B65@112.855,-16 ; v1(108.75,-76) CN4.B07@112.855,-76 ; v1(108.75,-61) CN4.B20@112.855,-61 ; v1(108.75,-50) CN4.B31@112.5,-50
  Bottom Layer w0.4: CN2.A31@-29.855,-31 v1(-26.25,-31) ; v1(32,-3.75) v1@32,-3.658
  Bottom Layer w0.7: CN2.A76@-29.855,-76 -27.605,-76 v1(-26.605,-75) ; CN2.A65@-29.855,-65 v1(-26.325,-65) ; CN2.A56@-29.855,-56 v1(-26.325,-56) ; CN2.A45@-29.855,-45 v1(-26.25,-45) ; CN2.A20@-29.855,-20 v1(-26.25,-20) ; CN2.A07@-29.855,-5 v1(-26.59,-5) ; CN3.A07@6,-91.35 v1(6,-85) ; v1(6,-4.75) CN1.A07@6,0 ; CN3.A20@21,-91.35 v1(21,-87.5) ; v1(21,-3.75) CN1.A20@21,0 ; CN3.A31@32,-91.35 v1(32,-87.5) ; v1(32,-3.75) CN1.A31@32,0 ; CN3.A45@46,-91.35 v1(46,-87.5) ; v1(46,-5) CN1.A45@46,0 ; CN3.A56@57,-91.35 57,-89.54 v1(57,-87.5) ; v1(57,-5) CN1.A56@57,0 ; CN3.A65@66,-91.35 v1(66,-87.5) ; v1(66,-5) CN1.A65@66,0 ; v1(77,-15.5) CN1.A76@77,0 ; CN3.A76@77,-91.35 v1(77,-86.25) ; v1(108.75,-36) CN4.A45@112.855,-36 ; v1(108.75,-25) CN4.A56@112.855,-25 ; v1(108.75,-16) CN4.A65@112.855,-16 ; v1(108.75,-6.75) 110.5,-5 CN4.A76@112.855,-5 ; v1(108.75,-76) CN4.A07@112.855,-76 ; v1(108.75,-61) CN4.A20@112.855,-61 ; v1(108.75,-50) CN4.A31@112.855,-50
  other v1: -12.5,-85 37.5,-85 47.5,-85 57.5,-85 67.5,-85 -15,-80 40,-80 50,-80 60,-80 70,-80 80,-80 -22.5,-75 -12.5,-75 12.5,-75 47.5,-75 57.5,-75 67.5,-75 87.5,-75 -25,-70 -15,-70 -22.5,-65 -25,-60 -15,-60 -22.5,-55 17.5,-55 22.5,-55 32.5,-55 60,-55 70,-55 -15,-50 57.5,-50 67.5,-50 97.5,-50 -22.5,-45 60,-45 95,-45 105,-45 -25,-40 57.5,-40 87.5,-40 97.5,-40 107.5,-40 85,-35 95,-35 105,-35 12.5,-32.5 77.5,-30 87.5,-30 97.5,-30 107.5,-30 20,-27.5 85,-25 95,-25 105,-25 77.5,-20 87.5,-20 97.5,-20 107.5,-20 95,-15 105,-15 87.5,-10 97.5,-10 107.5,-10 -12.5,-5 105,-5 87.5,0 97.5,0 -12.5,2.5
ID_Enable: CN1.A08 CN2.A08 CN3.A08 CN4.A08 | length 241.3
  Layer 2 w0.4: v2(7,-9.5) 7,-59.75 v2(10,-62.75) 91,-62.75 v2(102.5,-74.25)
  Bottom Layer w0.4: CN2.A08@-29.855,-6 -25.687,-6 -25.286,-6.402 -18.598,-6.402 -14,-11 5.5,-11 v2(7,-9.5) 7,-5.7 CN1.A08@7,0 ; CN3.A08@7,-91.35 7,-77.673 10,-74.673 v2(10,-62.75) ; v2(102.5,-74.25) 103.25,-75 CN4.A08@112.855,-75
Inrush_Lim.: CN1.B35 CN2.B35 pad.TP@-2.5,-35 | length 82.7
  Top Layer w0.4: CN2.B35@-29.855,-35 5.02,-35 36,-4.02 CN1.B35@36,0
M1_5V: CN2.A05 CN2.B05 JP1.6 | length 40.1
  Top Layer w0.7: CN2.B05@-29.855,-3 -12.75,-3 -12.25,-2.5 JP1.6@-10,-2.5
  Bottom Layer w0.7: CN2.A05@-29.855,-3 -12.75,-3 -12.25,-2.5 JP1.6@-10,-2.5
M1_ADC_1: CN2.A09 SB1.2 | length 85.1
  Top Layer w0.4: v2(21.963,-31.25) SB1.2@23.225,-31.25
  Layer 2 w0.4: v2(-17.5,-37.5) v2(-17.5,-8.75)
  Bottom Layer w0.4: CN2.A09@-29.855,-7 -25.312,-7 -25.302,-7.01 -19.24,-7.01 v2(-17.5,-8.75) ; v2(-17.5,-37.5) 15.713,-37.5 v2(21.963,-31.25)
M1_ADC_2: CN2.A10 SB4.2 | length 82.8
  Top Layer w0.4: v2(22,-38.75) SB4.2@23.263,-38.75
  Layer 2 w0.4: v2(-18.25,-38.25) v2(-18.25,-9.25)
  Bottom Layer w0.4: CN2.A10@-29.855,-8 -19.5,-8 v2(-18.25,-9.25) ; v2(-18.25,-38.25) 21.5,-38.25 v2(22,-38.75)
M1_ADC_3: CN2.A11 SB7.2 | length 87.1
  Top Layer w0.4: v2(21.25,-42.5) 21.25,-44.886 22.614,-46.25 SB7.2@23.263,-46.25
  Layer 2 w0.4: v2(-19,-39) v2(-19,-9.75)
  Bottom Layer w0.4: CN2.A11@-29.855,-9 -19.75,-9 v2(-19,-9.75) ; v2(-19,-39) 17.75,-39 v2(21.25,-42.5)
M1_ADC_4: CN2.B09 SB10.2 | length 101.8
  Top Layer w0.4: CN2.B09@-29.855,-7 -23,-7 v2(-19.75,-10.25) ; v2(30.713,-31.25) SB10.2@31.975,-31.25
  Layer 2 w0.4: v2(-19.75,-39.75) v2(-19.75,-10.25)
  Bottom Layer w0.4: v2(-19.75,-39.75) 17.5,-39.75 21,-43.25 23.75,-43.25 30.713,-36.287 30.713,-31.541
M1_ADC_5: CN2.B10 SB13.2 | length 96.3
  Top Layer w0.4: CN2.B10@-29.855,-8 -23.25,-8 v2(-20.5,-10.75) ; v2(30.75,-38.75) SB13.2@32.013,-38.75
  Layer 2 w0.4: v2(-20.5,-40.5) v2(-20.5,-10.75)
  Bottom Layer w0.4: v2(-20.5,-40.5) 17.25,-40.5 20.598,-43.848 23.998,-43.848 29.096,-38.75 v2(30.75,-38.75)
M1_ADC_6: CN2.B11 SB16.2 | length 94.9
  Top Layer w0.4: CN2.B11@-29.855,-9 -23.5,-9 v2(-21.25,-11.25) ; v2(30.75,-46.25) SB16.2@32.013,-46.25
  Layer 2 w0.4: v2(-21.25,-41.25) v2(-21.25,-11.25)
  Bottom Layer w0.4: v2(-21.25,-41.25) 17,-41.25 22,-46.25 v2(30.75,-46.25)
M1_BKIN: CN1.A12 CN2.A12 pad.TP@-6.25,-12 | length 50.5
  Bottom Layer w0.4: CN2.A12@-29.855,-12 5.582,-12 13,-4.582 CN1.A12@13,0
M1_BKIN2: CN1.B12 CN2.B12 pad.TP@-6.25,-12 | length 50.8
  Top Layer w0.4: CN2.B12@-29.855,-12 6.021,-12 13,-5.021 CN1.B12@13,0
M1_D_BRAKE: CN1.A30 CN2.A30 pad.TP@-6.25,-30 | length 75.2
  Bottom Layer w0.4: CN2.A30@-29.855,-30 4.287,-30 31,-3.287 CN1.A30@31,0
M1_Enable_A: CN1.A78 CN2.A78 pad.TP@12.5,-60.75 | length 149.8
  Layer 2 w0.4: v2(36.25,-47.5) 70.25,-13.5 v2(79.5,-13.5)
  Bottom Layer w0.4: CN2.A78@-29.855,-78 -12.058,-78 5.192,-60.75 23,-60.75 v2(36.25,-47.5) ; CN1.A78@79,0 79,-6.918 79.5,-7.418 v2(79.5,-13.5)
M1_Enable_B1: CN1.B77 CN2.B77 pad.TP@-2.5,-37 | length 163.7
  Top Layer w0.4: CN2.B77@-29.855,-77 -23,-77 -19.75,-73.75 -19.75,-43 -13.75,-37 4.712,-37 33.462,-8.25 v2(35,-8.25) ; CN1.B77@78,0 78,-7.5 v2(78.75,-8.25)
  Layer 2 w0.4: v2(35,-8.25) v2(78.75,-8.25)
M1_Enable_B2: CN1.B78 CN2.B78 pad.TP@-6.25,-38 | length 166.6
  Top Layer w0.4: CN2.B78@-29.855,-78 -23.154,-78 -19.152,-73.998 -19.152,-43.248 -13.904,-38 4.558,-38 33.558,-9 v2(35.75,-9) ; CN1.B78@79,0 79,-7.5 v2(80.5,-9)
  Layer 2 w0.4: v2(35.75,-9) v2(80.5,-9)
M1_Encoder_A: CN1.B16 CN2.B16 pad.TP@-6.25,-16 | length 56.1
  Top Layer w0.4: CN2.B16@-29.855,-16 5.404,-16 17,-4.404 CN1.B16@17,0
M1_Encoder_B: CN1.B17 CN2.B17 pad.TP@-2.5,-17 | length 57
  Top Layer w0.4: CN2.B17@-29.5,-17 5.25,-17 18,-4.25 CN1.B17@18,0
M1_Encoder_Z: CN1.B18 CN2.B18 pad.TP@-6.25,-18 | length 58.7
  Top Layer w0.4: CN2.B18@-29.855,-18 5.096,-18 18.958,-4.138 18.958,-0.042 CN1.B18@19,0
M1_Hall_H1: CN1.A18 CN2.A18 pad.TP@-6.25,-18 | length 58.5
  Bottom Layer w0.4: CN2.A18@-29.855,-18 4.658,-18 19,-3.658 CN1.A18@19,0
M1_Hall_H2: CN1.A19 CN2.A19 pad.TP@-2.5,-19 | length 59.8
  Bottom Layer w0.4: CN2.A19@-29.855,-19 4.503,-19 20,-3.503 CN1.A19@20,0
M1_Hall_H3: CN1.B19 CN2.B19 pad.TP@-2.5,-19 | length 60
  Top Layer w0.4: CN2.B19@-29.855,-19 4.942,-19 20,-3.942 CN1.B19@20,0
M1_Master_EN: CN1.A16 CN2.A16 pad.TP@-6.25,-16 | length 55.8
  Bottom Layer w0.4: CN2.A16@-29.855,-16 4.966,-16 17,-3.966 CN1.A16@17,0
M1_PWM_UH: CN1.A13 CN2.A13 pad.TP@-2.5,-13 | length 51.8
  Bottom Layer w0.4: CN2.A13@-29.855,-13 5.428,-13 14,-4.428 CN1.A13@14,0
M1_PWM_UL: CN1.B13 CN2.B13 pad.TP@-2.5,-13 | length 52.1
  Top Layer w0.4: CN2.B13@-29.855,-13 5.867,-13 14,-4.867 CN1.B13@14,0
M1_PWM_VH: CN1.A14 CN2.A14 pad.TP@-6.25,-14 | length 53.2
  Bottom Layer w0.4: CN2.A14@-29.855,-14 5.274,-14 15,-4.274 CN1.A14@15,0
M1_PWM_VL: CN1.B14 CN2.B14 pad.TP@-6.25,-14 | length 53.4
  Top Layer w0.4: CN2.B14@-29.855,-14 5.713,-14 15,-4.713 CN1.B14@15,0
M1_PWM_WH: CN1.A15 CN2.A15 pad.TP@-2.5,-15 | length 54.5
  Bottom Layer w0.4: CN2.A15@-29.855,-15 5.12,-15 16,-4.12 CN1.A15@16,0
M1_PWM_WL: CN1.B15 CN2.B15 pad.TP@-2.5,-15 | length 54.7
  Top Layer w0.4: CN2.B15@-29.855,-15 5.559,-15 16,-4.559 CN1.B15@16,0
M1_Res.Ex: CN1.B28 CN2.B28 pad.TP@-6.25,-28 | length 72.6
  Top Layer w0.4: CN2.B28@-29.855,-28 4.596,-28 29,-3.596 CN1.B28@29,0
M1_Resolv_Cos: CN1.B30 CN2.B30 pad.TP@-6.25,-30 | length 75.2
  Top Layer w0.4: CN2.B30@-29.855,-30 4.287,-30 31,-3.287 CN1.B30@31,0
M1_Resolv_Sin: CN1.B29 CN2.B29 pad.TP@-2.5,-29 | length 73.9
  Top Layer w0.4: CN2.B29@-29.855,-29 4.441,-29 30,-3.441 CN1.B29@30,0
M1_SHUNT1+: CN1.A21 CN2.A21 pad.TP@-2.5,-21 | length 62.9
  Bottom Layer w0.4: CN2.A21@-29.855,-21 5.058,-21 22,-4.058 CN1.A21@22,0
M1_SHUNT1-: CN1.B21 CN2.B21 pad.TP@-2.5,-21 | length 62.9
  Top Layer w0.4: CN2.B21@-29.855,-21 5.058,-21 22,-4.058 CN1.B21@22,0
M1_SHUNT2+: CN1.A22 CN2.A22 pad.TP@-6.25,-22 | length 64.3
  Bottom Layer w0.4: CN2.A22@-29.855,-22 4.904,-22 23,-3.904 CN1.A22@23,0
M1_SHUNT2-: CN1.B22 CN2.B22 pad.TP@-6.25,-22 | length 64.3
  Top Layer w0.4: CN2.B22@-29.855,-22 4.904,-22 23,-3.904 CN1.B22@23,0
M1_SHUNT3+: CN1.A23 CN2.A23 pad.TP@-2.5,-23 | length 65.6
  Bottom Layer w0.4: CN2.A23@-29.855,-23 4.75,-23 24,-3.75 CN1.A23@24,0
M1_SHUNT3-: CN1.B23 CN2.B23 pad.TP@-2.5,-23 | length 65.6
  Top Layer w0.4: CN2.B23@-29.855,-23 4.75,-23 24,-3.75 CN1.B23@24,0
M1_SPI1_MISO: CN2.B01 SB27.2 | length 71.5
  Top Layer w0.4: CN2.B01@-29.855,1 -18.75,1 -18,1.75 v2(-16,1.75) ; v2(-16,-46.25) SB27.2@-6.7,-46.25
  Layer 2 w0.4: v2(-16,-46.25) v2(-16,1.75)
M1_SPI1_MOSI: CN1.B02 CN2.B02 CN3.B02 CN4.B02 TP4.1 | length 243.2
  Top Layer w0.4: CN2.B02@-29.855,0 -18.25,0 -17.25,1 -7.75,1 -1.911,-4.839 -0.839,-4.839 v2(0,-4) 1,-3 CN1.B02@1,0 ; CN3.B02@1,-91.35 v2(1,-81.75) ; v2(101.75,-81.75) 105,-81.75 105.75,-81 CN4.B02@112.855,-81
  Layer 2 w0.4: v2(0,-4) 0.75,-4.75 0.75,-65.75 v2(2.25,-67.25) 4.25,-69.25 89.25,-69.25 v2(101.75,-81.75)
  Bottom Layer w0.4: v2(1,-81.75) 1,-68.5 v2(2.25,-67.25)
M1_SPI1_nSS: CN2.A01 SB24.2 SB25.2 | length 91.7
  Top Layer w0.4: v2(-14.5,-42) -13.75,-41.25 SB25.2@-6.737,-41.25 -6.573,-41.414 -6.573,-41.59 -5.011,-43.152 1.377,-43.152 SB24.2@11.975,-53.75
  Layer 2 w0.4: v2(-14.5,-42) v2(-14.5,1.75)
  Bottom Layer w0.4: CN2.A01@-29.5,1 -18.75,1 -17.25,2.5 -15.25,2.5 v2(-14.5,1.75)
M1_SPI1_SCK: CN1.A02 CN2.A02 CN3.A02 CN4.A02 TP3.1 | length 246.1
  Layer 2 w0.4: v2(1,-4) 1.5,-4.5 1.5,-65 v2(2.25,-65.75) 5,-68.5 89.5,-68.5 102,-81 v2(104.75,-81)
  Bottom Layer w0.4: CN2.A02@-29.855,0 -18.904,0 -18.066,0.839 -7.839,0.839 -2.152,-4.848 0.152,-4.848 v2(1,-4) CN1.A02@1,0 ; CN3.A02@1,-91.35 1,-83.596 -2.5,-80.096 -2.5,-71.332 0.326,-68.506 0.326,-67.674 v2(2.25,-65.75) ; v2(104.75,-81) CN4.A02@112.855,-81
M1_SPI2_MISO: CN2.B03 SB28.2 | length 72.7
  Top Layer w0.4: CN2.B03@-29.855,-1 -18,-1 v2(-16.75,0.25) ; v2(-16.75,-48.75) SB28.2@-6.7,-48.75
  Layer 2 w0.4: v2(-16.75,-48.75) v2(-16.75,0.25)
M1_SPI2_MOSI: CN1.B04 CN2.B04 CN3.B04 CN4.B04 TP8.1 | length 243.7
  Top Layer w0.4: CN2.B04@-29.855,-2 -18.154,-2 -16.566,-0.411 -7.339,-0.411 -1.652,-6.098 1.152,-6.098 v2(2.25,-5) 3,-4.25 CN1.B04@3,0 ; CN3.B04@3,-91.35 3,-80.25 3.75,-79.5 v2(3.75,-65.5) ; v2(102.25,-80) 103.25,-79 CN4.B04@112.855,-79
  Layer 2 w0.4: v2(2.25,-5) 2.25,-64 v2(3.75,-65.5) 6,-67.75 90,-67.75 v2(102.25,-80)
M1_SPI2_nSS: CN2.A03 SB23.2 SB26.2 | length 89.5
  Top Layer w0.4: v2(-15.25,-43.75) SB26.2@-6.737,-43.75 -6.573,-43.914 -6.573,-44.09 -5.011,-45.652 1.377,-45.652 SB23.2@11.975,-56.25
  Layer 2 w0.4: v2(-15.25,-43.75) v2(-15.25,-1)
  Bottom Layer w0.4: CN2.A03@-29.495,-1 v2(-15.25,-1)
M1_SPI2_SCK: CN1.A04 CN2.A04 CN3.A04 CN4.A04 TP7.1 | length 244.4
  Layer 2 w0.4: v2(3,-5.25) 3,-63.25 v2(3.75,-64) 6.75,-67 90.25,-67 v2(102.25,-79)
  Bottom Layer w0.4: CN2.A04@-29.495,-2 -15.404,-2 -13.654,-0.25 -7.596,-0.25 -0.346,-7.5 0.75,-7.5 v2(3,-5.25) CN1.A04@3,0 ; CN3.A04@3,-91.35 3,-64.75 v2(3.75,-64) ; v2(102.25,-79) CN4.A04@112.855,-79
M1_SPI_nSS: CN1.A77 CN2.A77 pad.TP@8.75,-59.75 SB23.1 SB24.1 | length 166
  Top Layer w0.4: SB23.1@12.95,-56.25 SB24.1@12.95,-53.75 16.25,-50.45 v2(16.25,-44.75)
  Layer 2 w0.4: v2(16.25,-44.75) 21.5,-39.5 22.082,-39.5 22.589,-38.994 22.589,-38.316 48.904,-12 v2(78,-12)
  Bottom Layer w0.4: CN2.A77@-29.495,-77 -11.904,-77 5.346,-59.75 12,-59.75 16.25,-55.5 v2(16.25,-44.75) ; v2(78,-12) CN1.A77@78,0
M1_TEMP_ID: CN1.A28 CN2.A28 pad.TP@-6.25,-28 | length 72.6
  Bottom Layer w0.4: CN2.A28@-29.855,-28 4.596,-28 29,-3.596 CN1.A28@29,0
M1_Timer_ETR: CN1.A17 CN2.A17 pad.TP@-2.5,-17 | length 57.1
  Bottom Layer w0.4: CN2.A17@-29.855,-17 4.812,-17 18,-3.812 CN1.A17@18,0
M1_VBUS: CN1.A29 CN2.A29 pad.TP@-2.5,-29 | length 73.9
  Bottom Layer w0.4: CN2.A29@-29.855,-29 4.441,-29 30,-3.441 CN1.A29@30,0
M1_VOL+_U: CN1.A25 CN2.A25 pad.TP@-2.5,-25 | length 68.6
  Bottom Layer w0.4: CN2.A25@-29.855,-25 5.058,-25 26,-4.058 CN1.A25@26,0
M1_VOL+_V: CN1.A26 CN2.A26 pad.TP@-6.25,-26 | length 69.9
  Bottom Layer w0.4: CN2.A26@-29.855,-26 4.904,-26 27,-3.904 CN1.A26@27,0
M1_VOL+_W: CN1.A27 CN2.A27 pad.TP@-2.5,-27 | length 71.2
  Bottom Layer w0.4: CN2.A27@-29.855,-27 4.75,-27 28,-3.75 CN1.A27@28,0
M1_VOL-_U: CN1.B25 CN2.B25 pad.TP@-2.5,-25 | length 68.6
  Top Layer w0.4: CN2.B25@-29.855,-25 5.058,-25 26,-4.058 CN1.B25@26,0
M1_VOL-_V: CN1.B26 CN2.B26 pad.TP@-6.267,-25.933 | length 69.9
  Top Layer w0.4: CN2.B26@-29.855,-26 4.904,-26 27,-3.904 CN1.B26@27,0
M1_VOL-_W: CN1.B27 CN2.B27 pad.TP@-2.5,-27 | length 71.2
  Top Layer w0.4: CN2.B27@-29.855,-27 4.75,-27 28,-3.75 CN1.B27@28,0
M2_5V: CN3.A05 CN3.B05 JP1.4 | length 104.1
  Top Layer w0.7: CN3.B05@4,-91.35 v1(4,-81.25)
  Layer 2 w0.7: JP1.4@-10,-5.04 -12.25,-7.29 -12.25,-65 v1(4,-81.25)
  Bottom Layer w0.7: CN3.A05@4,-91.35 v1(4,-81.25)
M2_ADC_1: CN3.A09 SB2.2 | length 63.9
  Top Layer w0.4: v2(8,-78.75) 8,-74.5 18.804,-63.696 18.804,-38.209 SB2.2@23.263,-33.75
  Bottom Layer w0.4: CN3.A09@8,-91.35 v2(8,-78.75)
M2_ADC_2: CN3.A10 SB5.2 | length 57.7
  Top Layer w0.4: v2(9,-77.5) 9,-74.5 19.402,-64.098 19.402,-42.252 20.404,-41.25 SB5.2@23.263,-41.25
  Bottom Layer w0.4: CN3.A10@9,-91.35 v2(9,-77.5)
M2_ADC_3: CN3.A11 SB8.2 | length 48.1
  Top Layer w0.4: v2(10,-76.25) 10,-74.5 20,-64.5 20,-52.013 SB8.2@23.263,-48.75
  Bottom Layer w0.4: CN3.A11@10,-91.35 v2(10,-76.25)
M2_ADC_4: CN3.B09 SB11.2 | length 67.8
  Top Layer w0.4: CN3.B09@8,-91.35 8,-81.596 29.054,-60.542 29.054,-38.696 30.75,-37 30.75,-34.5 31.5,-33.75 SB11.2@31.975,-33.75
M2_ADC_5: CN3.B10 SB14.2 | length 59.6
  Top Layer w0.4: CN3.B10@9,-91.35 9,-81.442 29.652,-60.79 29.652,-43.611 SB14.2@32.013,-41.25
M2_ADC_6: CN3.B11 SB17.2 | length 51.7
  Top Layer w0.4: CN3.B11@10,-91.35 10,-81.288 30.25,-61.038 30.25,-50.489 31.988,-48.75 SB17.2@32.013,-48.75
M2_BKIN: CN1.A37 CN3.A12 pad.TP@38,-52.5 | length 101.7
  Bottom Layer w0.4: CN3.A12@13,-91.35 13,-84.889 38,-59.889 CN1.A37@38,0
M2_BKIN2: CN1.B37 CN3.B12 pad.TP@38,-52.5 | length 101.7
  Top Layer w0.4: CN3.B12@13,-91.35 13,-82 38,-57 CN1.B37@38,0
